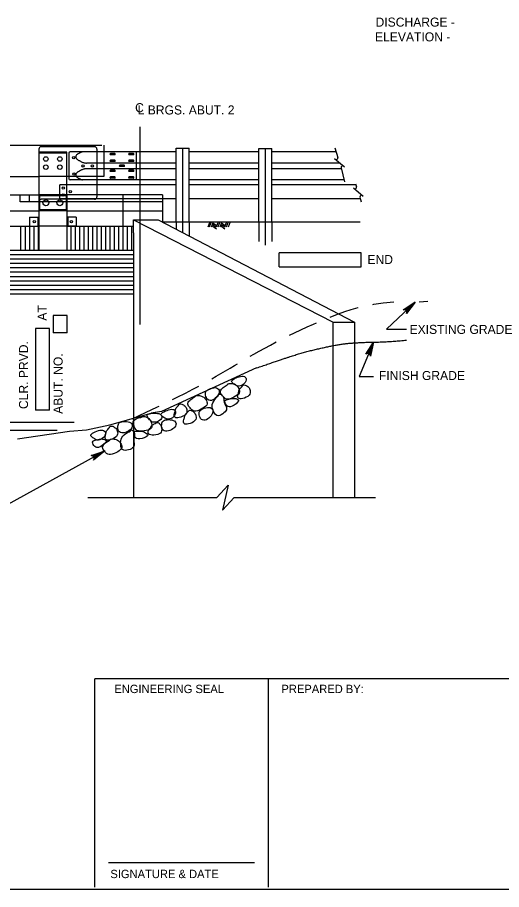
# Model space of a CAD drawing. Extents: x 638263 to 640360, y 293683 to 298655.
# Drawn here: x 638728.4 to 638888.9, y 297262.5 to 297551.6 of the extents above; entities that cross this region are included whole.
import ezdxf

# ---------------------------------------------------------------- set-up
doc = ezdxf.new("R2010")
doc.units = 0
for name, color, linetype in [('10', 7, 'Continuous'), ('2', 7, 'Continuous'), ('3', 7, 'Continuous'), ('4', 7, 'Continuous'), ('5', 7, 'Continuous'), ('8', 7, 'Continuous'), ('Level 25', 7, 'Continuous')]:
    doc.layers.add(name, color=color, linetype=linetype)

msp = doc.modelspace()

# ---------------------------------------------------------------- linework, layer by layer
at = {"layer": '2'}
for p, q in [((638583.44, 297509.28), (638756.44, 297509.28)), ((638757.09, 297509.28), (638757.09, 297506.97)), ((638744.78, 297506.96), (638735.54, 297506.96)), ((638735.54, 297506.96), (638735.54, 297492.72)), ((638744.78, 297506.58), (638735.54, 297506.58)), ((638744.78, 297492.72), (638744.78, 297506.96)), ((638745.51, 297506.61), (638745.51, 297498.11)), ((638757.09, 297506.98), (638745.88, 297506.98)), ((638767.68, 297506.98), (638757.09, 297506.98)), ((638757.09, 297506.96), (638757.09, 297498.88)), ((638760.7, 297506.47), (638759.22, 297506.47)), ((638760.7, 297506.01), (638759.22, 297506.01)), ((638766.88, 297506.47), (638765.4, 297506.47)), ((638766.88, 297506.01), (638765.4, 297506.01)), ((638767.75, 297506.98), (638767.75, 297497.74)), ((638781.02, 297506.98), (638767.75, 297506.98)), ((638808.42, 297506.98), (638785.35, 297506.98)), ((638834.04, 297506.98), (638812.74, 297506.98)), ((638757.09, 297503.28), (638751.34, 297503.28)), ((638781.02, 297503.28), (638757.09, 297503.28)), ((638760.7, 297504.25), (638759.22, 297504.25)), ((638760.7, 297503.79), (638759.22, 297503.79)), ((638766.88, 297504.25), (638765.4, 297504.25)), ((638766.88, 297503.79), (638765.4, 297503.79)), ((638808.42, 297503.28), (638785.35, 297503.28)), ((638835.36, 297503.28), (638812.74, 297503.28)), ((638757.09, 297501.43), (638751.34, 297501.43)), ((638781.02, 297501.43), (638757.09, 297501.43)), ((638760.7, 297500.93), (638759.22, 297500.93)), ((638760.7, 297500.46), (638759.22, 297500.46)), ((638763.79, 297502.59), (638762.32, 297502.59)), ((638763.79, 297502.13), (638762.32, 297502.13)), ((638766.88, 297500.93), (638765.4, 297500.93)), ((638766.88, 297500.46), (638765.4, 297500.46)), ((638808.42, 297501.43), (638785.35, 297501.43)), ((638835.8, 297501.43), (638812.74, 297501.43)), ((638695.15, 297498.88), (638735.54, 297498.88)), ((638744.78, 297498.88), (638735.54, 297498.88)), ((638754.78, 297498.88), (638744.78, 297498.88)), ((638754.79, 297497.74), (638745.88, 297497.74)), ((638757.09, 297498.88), (638754.78, 297498.88)), ((638781.02, 297497.74), (638754.79, 297497.74)), ((638760.7, 297498.71), (638759.22, 297498.71)), ((638760.7, 297498.25), (638759.22, 297498.25)), ((638766.88, 297498.71), (638765.4, 297498.71)), ((638766.88, 297498.25), (638765.4, 297498.25)), ((638808.42, 297497.74), (638785.35, 297497.74)), ((638836.72, 297497.74), (638812.74, 297497.74)), ((638742.43, 297491.46), (638742.43, 297496.08)), ((638754.79, 297496.08), (638742.43, 297496.08)), ((638781.02, 297496.08), (638754.79, 297496.08)), ((638808.42, 297496.08), (638785.35, 297496.08)), ((638840.66, 297496.08), (638812.74, 297496.08)), ((638695.15, 297492.72), (638735.54, 297492.72)), ((638729.37, 297490.41), (638729.37, 297492.72)), ((638732.46, 297490.41), (638732.46, 297492.72)), ((638744.78, 297492.72), (638735.54, 297492.72)), ((638735.54, 297492.72), (638735.54, 297474.4)), ((638744.61, 297492.44), (638735.73, 297492.44)), ((638735.73, 297492.44), (638735.73, 297487.82)), ((638744.61, 297492.44), (638744.61, 297487.82)), ((638776.52, 297492.72), (638744.78, 297492.72)), ((638744.78, 297492.72), (638744.78, 297474.4)), ((638754.79, 297492.72), (638754.79, 297492.06)), ((638776.51, 297490.41), (638729.35, 297490.41)), ((638776.51, 297491.46), (638742.41, 297491.46)), ((638781.02, 297491.46), (638776.52, 297491.46)), ((638808.42, 297491.46), (638785.35, 297491.46)), ((638842.1, 297491.46), (638812.74, 297491.46)), ((638695.15, 297487.52), (638735.54, 297487.52)), ((638744.78, 297487.52), (638735.54, 297487.52)), ((638744.61, 297487.82), (638735.73, 297487.82)), ((638732.45, 297485.42), (638735.54, 297485.42)), ((638732.45, 297485.42), (638732.45, 297482.33)), ((638735.18, 297485.42), (638735.18, 297482.33)), ((638735.54, 297485.42), (638735.54, 297482.33)), ((638747.87, 297485.42), (638744.78, 297485.42)), ((638744.78, 297485.42), (638744.78, 297482.33)), ((638745.14, 297485.42), (638745.14, 297482.33)), ((638747.87, 297485.42), (638747.87, 297482.33)), ((638732.45, 297482.33), (638735.54, 297482.33)), ((638744.78, 297482.33), (638735.54, 297482.33)), ((638747.87, 297482.33), (638744.78, 297482.33)), ((639261.46, 297262.46), (638475.46, 297262.46))]:
    msp.add_line(p, q, dxfattribs=at)
for centre, radius in [((638737.85, 297504.66), 0.748), ((638742.47, 297504.66), 0.748), ((638747.09, 297505.1), 0.385), ((638737.85, 297501.96), 0.748), ((638742.47, 297501.96), 0.748), ((638750.19, 297502.37), 0.385), ((638753.27, 297502.37), 0.385), ((638747.12, 297499.64), 0.385), ((638743.62, 297495.02), 0.385), ((638743.62, 297492.72), 0.385), ((638745.93, 297493.87), 0.385), ((638737.86, 297490.12), 0.978), ((638742.47, 297490.12), 0.978), ((638734, 297483.88), 0.385), ((638746.32, 297483.88), 0.385)]:
    msp.add_circle(centre, radius, dxfattribs=at)
for centre, radius, start, end in [((638745.88, 297506.61), 0.369, 90, 180), ((638748.65, 297505.35), 0.916, 120.3532, 238.6149), ((638750.97, 297502.7), 4.42, 125.3229, 129.0151), ((638748.97, 297505.53), 0.955, 117.3798, 125.3229), ((638763.15, 297478.14), 31.8, 116.5749, 117.3798), ((638750.01, 297504.42), 2.42, 113.6547, 116.5749), ((638751.42, 297501.2), 5.93, 112.3149, 113.6547), ((638773.74, 297446.81), 64.73, 111.9093, 112.3149), ((638750.29, 297505.11), 1.88, 108.4934, 111.9093), ((638752.92, 297497.25), 10.17, 107.0234, 108.4934), ((638759.36, 297506.24), 0.269, 120.8559, 239.1441), ((638760.56, 297506.24), 0.269, 300.8559, 59.1441), ((638765.54, 297506.24), 0.269, 120.8559, 239.1441), ((638766.74, 297506.24), 0.269, 300.8559, 59.1441), ((638751.4, 297508.3), 4.94, 229.2007, 233.1182), ((638749.09, 297505.22), 1.09, 233.1182, 241.475), ((638936.16, 297849.41), 392.83, 241.475, 241.5275), ((638688.64, 297393.02), 126.36, 61.435, 61.5275), ((638694.04, 297402.92), 115.08, 61.2499, 61.435), ((638759.71, 297522.63), 21.45, 241.2499, 241.6785), ((638749.84, 297504.31), 0.644, 241.6785, 249.7671), ((638755.9, 297520.76), 18.18, 249.7671, 251.2889), ((638751.08, 297506.52), 3.14, 251.2889, 252.6389), ((638777.58, 297591.29), 91.96, 252.6389, 252.8885), ((638751.16, 297505.47), 2.16, 252.8885, 261.633), ((638751.58, 297508.31), 5.03, 261.633, 267.3571), ((638759.36, 297504.02), 0.269, 120.8559, 239.1441), ((638760.56, 297504.02), 0.269, 300.8559, 59.1441), ((638765.54, 297504.02), 0.269, 120.8559, 239.1441), ((638766.74, 297504.02), 0.269, 300.8559, 59.1441), ((638748.65, 297499.37), 0.916, 121.3851, 239.6468), ((638751.4, 297496.41), 4.94, 126.8818, 130.7993), ((638749.09, 297499.49), 1.09, 118.525, 126.8818), ((638936.16, 297155.3), 392.83, 118.4725, 118.525), ((638688.64, 297611.7), 126.36, 298.4725, 298.565), ((638694.04, 297601.79), 115.08, 298.565, 298.7501), ((638759.71, 297482.09), 21.45, 118.3215, 118.7501), ((638749.84, 297500.41), 0.644, 110.2329, 118.3215), ((638755.9, 297483.96), 18.18, 108.7111, 110.2329), ((638751.08, 297498.19), 3.14, 107.3611, 108.7111), ((638777.58, 297413.42), 91.96, 107.1115, 107.3611), ((638751.16, 297499.25), 2.16, 98.367, 107.1115), ((638751.58, 297496.41), 5.03, 92.6429, 98.367), ((638759.36, 297500.7), 0.269, 120.8559, 239.1441), ((638760.56, 297500.7), 0.269, 300.8559, 59.1441), ((638762.46, 297502.36), 0.269, 120.8559, 239.1441), ((638763.66, 297502.36), 0.269, 300.8559, 59.1441), ((638765.54, 297500.7), 0.269, 120.8559, 239.1441), ((638766.74, 297500.7), 0.269, 300.8559, 59.1441), ((638745.88, 297498.11), 0.369, 180, 270), ((638750.97, 297502.01), 4.42, 230.9849, 234.6771), ((638748.97, 297499.19), 0.955, 234.6771, 242.6202), ((638763.15, 297526.58), 31.8, 242.6202, 243.4251), ((638750.01, 297500.3), 2.42, 243.4251, 246.3453), ((638751.42, 297503.52), 5.93, 246.3453, 247.6851), ((638773.74, 297557.91), 64.73, 247.6851, 248.0907), ((638750.29, 297499.61), 1.88, 248.0907, 251.5066), ((638752.92, 297507.46), 10.17, 251.5066, 252.9766), ((638759.36, 297498.48), 0.269, 120.8559, 239.1441), ((638760.56, 297498.48), 0.269, 300.8559, 59.1441), ((638765.54, 297498.48), 0.269, 120.8559, 239.1441), ((638766.74, 297498.48), 0.269, 300.8559, 59.1441)]:
    msp.add_arc(centre, radius, start, end, dxfattribs=at)
at = {"layer": '3'}
for p, q in [((638781.02, 297508.24), (638785.35, 297508.24)), ((638781.02, 297483.77), (638781.02, 297508.24)), ((638783.18, 297508.24), (638783.18, 297480.27)), ((638785.35, 297483.77), (638785.35, 297508.24)), ((638808.42, 297508.16), (638812.74, 297508.16)), ((638808.42, 297483.77), (638808.42, 297508.16)), ((638810.58, 297508.16), (638810.58, 297476.08)), ((638812.74, 297483.77), (638812.74, 297508.16)), ((638833.6, 297508.34), (638834.61, 297505.19)), ((638833.54, 297504.8), (638836.81, 297502.06)), ((638835.73, 297501.72), (638836.88, 297497.13)), ((638839.78, 297495.08), (638843.05, 297492.34)), ((638840.53, 297496.46), (638840.85, 297495.47)), ((638763.51, 297482.33), (638763.51, 297492.72)), ((638776.52, 297492.72), (638776.52, 297483.77)), ((638841.97, 297492), (638842.34, 297490.49)), ((638744.76, 297487.52), (638776.52, 297487.52)), ((638766.86, 297484.49), (638833.06, 297450.61)), ((638766.86, 297484.49), (638775.07, 297484.49)), ((638766.86, 297480.17), (638766.86, 297484.49)), ((638775.07, 297484.49), (638840.19, 297450.61)), ((638776.45, 297483.77), (638842, 297483.77)), ((638781.02, 297483.77), (638781.02, 297481.4)), ((638785.35, 297483.77), (638785.35, 297479.15)), ((638792.15, 297483.77), (638791.48, 297482.02)), ((638792.69, 297483.78), (638792.03, 297482.02)), ((638793.33, 297483.79), (638792.67, 297482.03)), ((638793.04, 297483.02), (638794.33, 297482.12)), ((638793.2, 297483.45), (638794.49, 297482.55)), ((638794.96, 297483.79), (638794.3, 297482.06)), ((638795.51, 297483.8), (638794.85, 297482.07)), ((638796.14, 297483.8), (638795.49, 297482.08)), ((638795.85, 297483.03), (638797.14, 297482.13)), ((638796.01, 297483.46), (638797.3, 297482.56)), ((638797.77, 297483.8), (638797.11, 297482.07)), ((638798.32, 297483.81), (638797.66, 297482.08)), ((638798.95, 297483.81), (638798.3, 297482.09)), ((638808.42, 297483.77), (638808.42, 297477.28)), ((638812.74, 297483.77), (638812.74, 297477.28)), ((638695.15, 297482.33), (638735.54, 297482.33)), ((638744.78, 297482.33), (638766.86, 297482.33)), ((638766.86, 297480.17), (638766.86, 297418.67)), ((638792.87, 297482.57), (638794.37, 297481.53)), ((638795.68, 297482.58), (638797.18, 297481.54)), ((638574.49, 297474.4), (638766.86, 297474.4)), ((638574.49, 297459.98), (638766.86, 297459.98)), ((638860.22, 297457.21), (638850.73, 297448.28)), ((638833.06, 297450.61), (638840.19, 297450.61)), ((638833.06, 297442.76), (638833.06, 297450.61)), ((638840.19, 297450.61), (638840.19, 297443.67)), ((638850.73, 297448.28), (638857.33, 297448.28)), ((638833.06, 297392.39), (638833.06, 297442.76)), ((638840.19, 297443.67), (638840.19, 297392.39)), ((638846.45, 297443.93), (638841.69, 297432.53)), ((638807.71, 297435.38), (638776.12, 297420.89)), ((638841.69, 297432.53), (638846.46, 297432.53)), ((638776.12, 297420.89), (638772.8, 297420.39)), ((638766.86, 297418.67), (638766.86, 297392.39)), ((638580.85, 297414.78), (638741.58, 297414.78)), ((638794.47, 297392.39), (638798.31, 297396.56)), ((638798.31, 297396.56), (638796.38, 297388.22)), ((638751.78, 297392.39), (638794.47, 297392.39)), ((638796.38, 297388.22), (638800.23, 297392.39)), ((638800.23, 297392.39), (638847.06, 297392.39))]:
    msp.add_line(p, q, dxfattribs=at)
msp.add_lwpolyline([(638844.86, 297441.39), (638845.77, 297441.01), (638846.45, 297443.93)], close=True, dxfattribs=at)
for centre, start, end in [((638834.11, 297505.03), 227.8504, 17.8504), ((638836.25, 297501.84), 49.9832, 192.5218), ((638836.25, 297501.84), 49.9832, 49.9972), ((638840.35, 297495.31), 227.8504, 17.8504), ((638842.49, 297492.12), 49.9832, 192.5218), ((638842.49, 297492.12), 49.9832, 49.9972)]:
    msp.add_arc(centre, 0.533, start, end, dxfattribs=at)
for points, degree in [([(638807.71, 297435.38), (638815.49, 297438.06), (638822.64, 297440.39), (638829.78, 297442.14), (638836.53, 297443.45), (638842.88, 297443.88), (638851.42, 297444.03), (638857.38, 297444.61)], 2), ([(638799.58, 297430.54), (638799.82, 297430.29), (638800.68, 297429.73), (638801.79, 297429.09), (638803.77, 297430.03), (638804.53, 297431.96), (638803.44, 297432.86), (638801.42, 297432.42), (638799.24, 297431.28), (638799.34, 297430.8), (638799.58, 297430.54)], 3), ([(638790.94, 297427.65), (638790.66, 297427.28), (638790.69, 297426.44), (638791.32, 297424.61), (638793.16, 297424.48), (638794.91, 297426.1), (638795.61, 297427.73), (638794.64, 297429.07), (638792.37, 297428.67), (638791.22, 297428.02), (638790.94, 297427.65)], 3), ([(638798.16, 297429.99), (638798.11, 297429.9), (638797.78, 297429.62), (638796.19, 297428.7), (638795.39, 297427.27), (638796.4, 297426.22), (638797.6, 297424.59), (638800.18, 297425.59), (638802.4, 297427), (638801.85, 297428.6), (638801.06, 297429.73), (638799.46, 297430.33), (638798.11, 297430.13), (638798.22, 297430.07), (638798.16, 297429.99)], 3), ([(638801.7, 297427.05), (638801.63, 297426.74), (638801.33, 297426.38), (638801.48, 297425.16), (638802.82, 297424.99), (638805.72, 297426.24), (638805.62, 297427.99), (638805.11, 297429.09), (638803.85, 297429.8), (638803.2, 297429.83), (638802.9, 297429.22), (638801.73, 297428.18), (638801.76, 297427.35), (638801.7, 297427.05)], 3), ([(638787.39, 297426.01), (638787.33, 297425.92), (638787, 297425.64), (638785.41, 297424.72), (638784.62, 297423.29), (638785.62, 297422.24), (638786.83, 297420.61), (638789.4, 297421.61), (638791.62, 297423.02), (638791.08, 297424.62), (638790.29, 297425.74), (638788.68, 297426.35), (638787.34, 297426.14), (638787.44, 297426.09), (638787.39, 297426.01)], 3), ([(638795.26, 297426.68), (638795.12, 297426.59), (638795.01, 297426.13), (638792.74, 297423.82), (638792.99, 297421.61), (638794.39, 297419.03), (638796.59, 297420.04), (638798, 297421.54), (638797.53, 297422.92), (638796.78, 297423.93), (638796.93, 297425.77), (638795.84, 297426.67), (638795.4, 297426.77), (638795.26, 297426.68)], 3), ([(638797.71, 297424.76), (638797.29, 297424.62), (638796.98, 297424.51), (638797.69, 297422.46), (638799.41, 297422.28), (638802.53, 297424.75), (638800.69, 297425.28), (638799.5, 297425.38), (638798.13, 297424.91), (638797.71, 297424.76)], 3), ([(638780.67, 297420.75), (638780.61, 297420.45), (638780.3, 297420.09), (638780.46, 297418.86), (638781.8, 297418.69), (638784.69, 297419.94), (638784.6, 297421.7), (638784.09, 297422.8), (638782.83, 297423.51), (638782.17, 297423.54), (638781.87, 297422.92), (638780.7, 297421.89), (638780.74, 297421.05), (638780.67, 297420.75)], 3), ([(638788.83, 297421.1), (638788.56, 297420.73), (638788.59, 297419.89), (638789.22, 297418.06), (638791.06, 297417.93), (638792.81, 297419.55), (638793.51, 297421.18), (638792.54, 297422.52), (638790.27, 297422.12), (638789.11, 297421.47), (638788.83, 297421.1)], 3), ([(638769.97, 297419.24), (638769.89, 297419.18), (638769.49, 297419.02), (638767.69, 297418.67), (638766.47, 297417.57), (638767.08, 297416.25), (638767.69, 297414.32), (638770.45, 297414.43), (638773.01, 297415.04), (638773.01, 297416.73), (638772.63, 297418.05), (638771.31, 297419.15), (638769.97, 297419.39), (638770.05, 297419.3), (638769.97, 297419.24)], 3), ([(638771.49, 297419.31), (638771.63, 297418.99), (638772.27, 297418.18), (638773.11, 297417.22), (638775.29, 297417.46), (638776.63, 297419.04), (638775.9, 297420.24), (638773.85, 297420.49), (638771.41, 297420.12), (638771.35, 297419.63), (638771.49, 297419.31)], 3), ([(638776.19, 297419.56), (638776.43, 297419.31), (638777.29, 297418.75), (638778.4, 297418.11), (638780.38, 297419.05), (638781.14, 297420.98), (638780.05, 297421.88), (638778.03, 297421.44), (638775.85, 297420.3), (638775.95, 297419.82), (638776.19, 297419.56)], 3), ([(638783.74, 297418.63), (638783.67, 297418.33), (638783.37, 297417.97), (638783.52, 297416.74), (638784.87, 297416.57), (638787.76, 297417.82), (638787.67, 297419.58), (638787.15, 297420.68), (638785.89, 297421.39), (638785.24, 297421.42), (638784.94, 297420.81), (638783.77, 297419.77), (638783.81, 297418.93), (638783.74, 297418.63)], 3), ([(638762.29, 297417.26), (638761.91, 297417), (638761.67, 297416.19), (638761.67, 297414.26), (638763.37, 297413.54), (638765.55, 297414.5), (638766.74, 297415.82), (638766.26, 297417.4), (638763.98, 297417.75), (638762.67, 297417.52), (638762.29, 297417.26)], 3), ([(638772.36, 297415.31), (638772.2, 297415.05), (638771.79, 297414.8), (638771.54, 297413.59), (638772.76, 297413), (638775.9, 297413.24), (638776.38, 297414.93), (638776.25, 297416.14), (638775.29, 297417.22), (638774.68, 297417.46), (638774.2, 297416.97), (638772.76, 297416.38), (638772.52, 297415.57), (638772.36, 297415.31)], 3), ([(638776.8, 297417.87), (638776.42, 297417.61), (638776.18, 297416.8), (638776.18, 297414.87), (638777.88, 297414.14), (638780.06, 297415.11), (638781.25, 297416.43), (638780.77, 297418.01), (638778.49, 297418.36), (638777.19, 297418.13), (638776.8, 297417.87)], 3), ([(638752.94, 297412.65), (638753.18, 297412.4), (638754.04, 297411.84), (638755.15, 297411.2), (638757.13, 297412.14), (638757.89, 297414.07), (638756.8, 297414.97), (638754.78, 297414.53), (638752.6, 297413.39), (638752.7, 297412.91), (638752.94, 297412.65)], 3), ([(638757.74, 297413.38), (638757.67, 297413.08), (638757.37, 297412.72), (638757.52, 297411.49), (638758.86, 297411.32), (638761.76, 297412.57), (638761.66, 297414.33), (638761.15, 297415.43), (638759.89, 297416.14), (638759.24, 297416.17), (638758.94, 297415.55), (638757.77, 297414.52), (638757.8, 297413.68), (638757.74, 297413.38)], 3), ([(638766.24, 297414.81), (638766.08, 297414.77), (638765.82, 297414.37), (638762.93, 297412.93), (638762.45, 297410.75), (638762.93, 297407.85), (638765.34, 297408.09), (638767.17, 297409.06), (638767.17, 297410.51), (638766.79, 297411.72), (638767.52, 297413.41), (638766.79, 297414.62), (638766.4, 297414.85), (638766.24, 297414.81)], 3), ([(638767.84, 297414.45), (638767.4, 297414.45), (638767.08, 297414.45), (638767.08, 297412.27), (638768.65, 297411.55), (638772.4, 297412.87), (638770.83, 297413.97), (638769.74, 297414.45), (638768.29, 297414.45), (638767.84, 297414.45)], 3), ([(638753.88, 297411.29), (638753.46, 297411.14), (638753.16, 297411.04), (638753.86, 297408.98), (638755.58, 297408.81), (638758.7, 297411.28), (638756.86, 297411.8), (638755.67, 297411.91), (638754.3, 297411.43), (638753.88, 297411.29)], 3), ([(638759.11, 297411.61), (638759.06, 297411.53), (638758.72, 297411.24), (638757.14, 297410.32), (638756.34, 297408.89), (638757.35, 297407.84), (638758.55, 297406.21), (638761.13, 297407.22), (638763.35, 297408.63), (638762.8, 297410.23), (638762.01, 297411.35), (638760.41, 297411.96), (638759.06, 297411.75), (638759.17, 297411.7), (638759.11, 297411.61)], 3)]:
    msp.add_open_spline(points, degree=degree, dxfattribs=at)
at = {"layer": '4'}
for p, q in [((638769.01, 297515.36), (638769.01, 297449.75)), ((638842.34, 297473.55), (638815.19, 297473.55)), ((638815.19, 297468.85), (638815.19, 297473.55)), ((638842.34, 297468.85), (638842.34, 297473.55)), ((638815.19, 297468.85), (638842.34, 297468.85)), ((638740.23, 297452.77), (638740.23, 297447.02)), ((638744.93, 297452.77), (638740.23, 297452.77)), ((638744.93, 297447.02), (638744.93, 297452.77)), ((638734.38, 297448.51), (638734.38, 297421.36)), ((638739.09, 297448.51), (638734.38, 297448.51)), ((638739.09, 297421.36), (638739.09, 297448.51)), ((638744.93, 297447.02), (638740.23, 297447.02)), ((638739.09, 297421.36), (638734.38, 297421.36)), ((638716.39, 297417.42), (638747.22, 297417.42)), ((638757.31, 297407.83), (638717.09, 297385.6)), ((638754.05, 297263.21), (638754.05, 297332.31)), ((638892.25, 297332.31), (638754.05, 297332.31)), ((638811.64, 297263.21), (638811.64, 297332.31)), ((638807.03, 297271.29), (638758.66, 297271.29))]:
    msp.add_line(p, q, dxfattribs=at)
for points in [[(638860.22, 297457.21), (638857.42, 297453.38), (638857.52, 297453.8), (638857.44, 297454.16), (638857.26, 297454.42), (638857.01, 297454.61), (638856.66, 297454.71), (638856.23, 297454.65), (638860.22, 297457.21), (638856.66, 297454.71), (638857.01, 297454.61), (638860.22, 297457.21), (638857.26, 297454.42), (638857.44, 297454.16), (638860.22, 297457.21), (638857.52, 297453.8)], [(638846.45, 297443.93), (638845.46, 297439.29), (638845.37, 297439.72), (638845.16, 297440.01), (638844.89, 297440.18), (638844.58, 297440.25), (638844.22, 297440.2), (638843.85, 297439.96), (638846.45, 297443.93), (638844.22, 297440.2), (638844.58, 297440.25), (638846.45, 297443.93), (638844.89, 297440.18), (638845.16, 297440.01), (638846.45, 297443.93), (638845.37, 297439.72)], [(638728.43, 297411.86), (638745.65, 297414.47), (638751.33, 297414.81), (638759.06, 297416.48), (638772.8, 297420.39)], [(638757.31, 297407.83), (638753.65, 297404.81), (638753.85, 297405.2), (638753.86, 297405.57), (638753.76, 297405.87), (638753.56, 297406.11), (638753.24, 297406.3), (638752.81, 297406.34), (638757.31, 297407.83), (638753.24, 297406.3), (638753.56, 297406.11), (638757.31, 297407.83), (638753.76, 297405.87), (638753.86, 297405.57), (638757.31, 297407.83), (638753.85, 297405.2)]]:
    msp.add_lwpolyline(points, dxfattribs=at)
at = {"layer": '5'}
for p, q in [((638729.48, 297482.33), (638729.48, 297474.4)), ((638730.93, 297482.33), (638730.93, 297474.4)), ((638732.37, 297482.33), (638732.37, 297474.4)), ((638733.82, 297482.33), (638733.82, 297474.4)), ((638735.26, 297482.33), (638735.26, 297474.4)), ((638746.07, 297482.33), (638746.07, 297474.4)), ((638747.51, 297482.33), (638747.51, 297474.4)), ((638748.95, 297482.33), (638748.95, 297474.4)), ((638750.39, 297482.33), (638750.39, 297474.4)), ((638751.83, 297482.33), (638751.83, 297474.4)), ((638753.28, 297482.33), (638753.28, 297474.4)), ((638754.72, 297482.33), (638754.72, 297474.4)), ((638756.16, 297482.33), (638756.16, 297474.4)), ((638757.6, 297482.33), (638757.6, 297474.4)), ((638759.04, 297482.33), (638759.04, 297474.4)), ((638760.48, 297482.33), (638760.48, 297474.4)), ((638761.93, 297482.33), (638761.93, 297474.4)), ((638763.37, 297482.33), (638763.37, 297474.4)), ((638764.81, 297482.33), (638764.81, 297474.4)), ((638766.25, 297482.33), (638766.25, 297474.4)), ((638574.49, 297472.96), (638766.86, 297472.96)), ((638574.49, 297471.52), (638766.86, 297471.52)), ((638574.49, 297470.07), (638766.86, 297470.07)), ((638574.49, 297468.63), (638766.86, 297468.63)), ((638574.49, 297467.19), (638766.86, 297467.19)), ((638574.49, 297465.75), (638766.86, 297465.75)), ((638574.49, 297464.31), (638766.86, 297464.31)), ((638574.49, 297462.87), (638766.86, 297462.87)), ((638574.49, 297461.42), (638766.86, 297461.42))]:
    msp.add_line(p, q, dxfattribs=at)
at = {"layer": '8'}
for p, q in [((638846.52, 297456.51), (638849.62, 297456.94)), ((638849.62, 297456.94), (638853.14, 297457.3)), ((638861.6, 297457.3), (638864.43, 297457.48)), ((638834.89, 297453.32), (638836.96, 297454.07)), ((638836.96, 297454.07), (638839.08, 297454.77)), ((638839.08, 297454.77), (638841.33, 297455.41)), ((638841.33, 297455.41), (638841.37, 297455.42)), ((638846.19, 297456.45), (638846.52, 297456.51)), ((638832.07, 297452.23), (638832.82, 297452.52)), ((638832.82, 297452.52), (638834.89, 297453.32)), ((638822.32, 297448.02), (638824.42, 297448.98)), ((638824.42, 297448.98), (638826.52, 297449.92)), ((638826.52, 297449.92), (638827.52, 297450.35)), ((638818.58, 297446.23), (638820.25, 297447.04)), ((638820.25, 297447.04), (638822.32, 297448.02)), ((638810.38, 297441.95), (638812.27, 297442.97)), ((638812.27, 297442.97), (638814.2, 297444)), ((638805.58, 297439.25), (638806.77, 297439.93)), ((638806.77, 297439.93), (638808.54, 297440.93)), ((638808.54, 297440.93), (638810.38, 297441.95)), ((638800.39, 297436.21), (638801.33, 297436.77)), ((638795.89, 297433.55), (638797.42, 297434.45)), ((638797.42, 297434.45), (638798.91, 297435.33)), ((638798.91, 297435.33), (638800.39, 297436.21)), ((638792.84, 297431.79), (638794.29, 297432.63)), ((638794.29, 297432.63), (638795.89, 297433.55)), ((638784.15, 297427.06), (638786.6, 297428.35)), ((638786.6, 297428.35), (638788.54, 297429.39)), ((638779.8, 297424.87), (638781.41, 297425.66)), ((638781.41, 297425.66), (638784.15, 297427.06)), ((638770.88, 297420.59), (638774.82, 297422.44)), ((638774.82, 297422.44), (638775.38, 297422.71)), ((638766.46, 297418.55), (638770.88, 297420.59))]:
    msp.add_line(p, q, dxfattribs=at)
at = {"layer": 'Level 25'}
for p, q in [((638735.54, 297507.93), (638735.54, 297506.96)), ((638754.02, 297508.7), (638736.31, 297508.7)), ((638754.79, 297507.93), (638754.79, 297506.97)), ((638754.79, 297506.97), (638754.79, 297497.73)), ((638754.79, 297497.73), (638754.79, 297492.72)), ((638754.02, 297491.29), (638736.31, 297491.29))]:
    msp.add_line(p, q, dxfattribs=at)
for centre, start, end in [((638736.31, 297507.93), 90, 180), ((638754.02, 297507.93), 0, 90), ((638736.31, 297492.06), 180, 270), ((638754.02, 297492.06), 270, 0)]:
    msp.add_arc(centre, 0.77, start, end, dxfattribs=at)

# ---------------------------------------------------------------- texts
at = {"layer": '10'}
for s, p in [('ENGINEERING SEAL', (638760.53, 297327.59)), ('PREPARED BY:', (638815.93, 297327.59)), ('SIGNATURE & DATE', (638759.23, 297266.25))]:
    msp.add_text(s, height=2.7634, dxfattribs=at).set_placement(p)
at = {"layer": '4'}
for s, p in [('   DISCHARGE - ', (638843.78, 297548.53)), ('   ELEVATION - ', (638843.6, 297543.64)), ('C', (638767.41, 297520.16)), ('L BRGS. ABUT. 2', (638768.27, 297519.41)), ('END', (638844.44, 297469.83)), ('EXISTING GRADE', (638858.4, 297446.66)), ('FINISH GRADE', (638848.24, 297431.37))]:
    msp.add_text(s, height=3, dxfattribs=at).set_placement(p)
for s, p in [('AT', (638738.14, 297451.05)), ('CLR. PRVD.', (638731.94, 297421.75)), ('ABUT. NO. ', (638743.4, 297420.16))]:
    msp.add_text(s, height=3, rotation=90, dxfattribs=at).set_placement(p)

doc.saveas('drawing.dxf')
